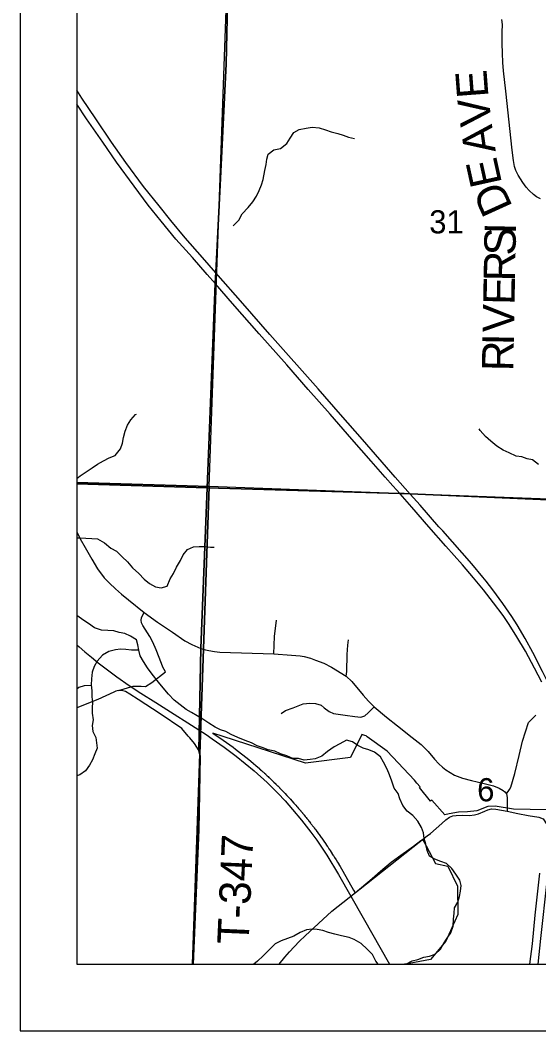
# Model space of a CAD drawing. Extents: x 0 to 34, y 0 to 22.
# Drawn here: x 2.735 to 3.672, y 14 to 15.827 of the extents above; entities that cross this region are included whole.
import ezdxf

# ---------------------------------------------------------------- set-up
doc = ezdxf.new("R2010")
doc.units = 0
for name, color, linetype in [('GM_X_Corporation', 7, 'Continuous'), ('GM_X_County_Road', 7, 'Continuous'), ('GM_X_Minor_River', 7, 'Continuous'), ('GM_X_Rail_Line', 7, 'Continuous'), ('GM_X_Section_Text', 7, 'Continuous'), ('GM_X_State_Route', 7, 'Continuous'), ('GM_X_Township_Road', 7, 'Continuous'), ('GM_X_Township_Road_Text', 7, 'Continuous'), ('SH_Data', 7, 'Continuous')]:
    doc.layers.add(name, color=color, linetype=linetype)

msp = doc.modelspace()

# ---------------------------------------------------------------- linework, layer by layer
at = {"layer": 'GM_X_Corporation'}
for points in [[(7.1023, 20.9204), (2.837, 20.9204), (2.837, 14.1204), (9.637, 14.1204), (9.637, 20.9204), (9.4036, 20.9204), (9.4022, 20.8667), (9.2273, 20.8723), (9.1354, 20.8749), (9.124, 20.8753), (8.9858, 20.878), (8.9676, 20.8785), (8.8663, 20.881), (8.6259, 20.8892), (8.5535, 20.8914), (8.5421, 20.8915), (8.4667, 20.8934), (8.0602, 20.9055), (7.9522, 20.9084), (7.1104, 20.9188)], [(3.3169, 20.9204), (2.837, 20.9204), (2.837, 14.9888), (3.0725, 14.9816), (3.0874, 15.351), (3.0879, 15.3623), (3.0883, 15.3712), (3.1072, 15.7483), (3.1177, 16.2414), (3.14, 16.6736), (3.1852, 17.7826), (3.1864, 17.8248), (3.233, 19.0394), (3.2586, 19.6098), (3.2623, 19.6596), (3.2721, 19.8755), (3.2728, 19.892), (3.2744, 19.9301), (3.2774, 20.0014), (3.2794, 20.0412), (3.3026, 20.5526), (3.3089, 20.7046), (3.3168, 20.9187)], [(2.837, 16.015), (2.837, 14.9913), (3.0765, 14.9841), (3.1126, 15.9984), (3.1125, 16.0117)], [(3.1126, 15.9984), (4.1402, 15.964), (4.1106, 14.9455), (3.0765, 14.9841)], [(2.837, 14.9913), (2.837, 14.1204), (3.0463, 14.1204), (3.0765, 14.9841)], [(2.837, 14.9888), (2.837, 14.1204), (3.0474, 14.1204), (3.0575, 14.3635), (3.0603, 14.4964), (3.0579, 14.5066), (3.0614, 14.6917), (3.0725, 14.9816)], [(3.0463, 14.1204), (4.0849, 14.1204), (4.1106, 14.9455), (3.0765, 14.9841)]]:
    msp.add_lwpolyline(points, close=True, dxfattribs=at)
for points in [[(3.1177, 16.2414), (3.1072, 15.7483), (3.0883, 15.3712), (3.0879, 15.3623), (3.0874, 15.351), (3.0725, 14.9816), (3.4212, 14.9717), (3.4288, 14.9714), (3.4395, 14.971), (3.7996, 14.9551), (3.9669, 14.9486), (3.9713, 14.9485), (4.1071, 14.9452), (4.1362, 14.9446), (4.18, 14.9435), (4.3471, 14.9395), (4.3478, 14.9395), (4.5297, 14.9322), (4.6565, 14.9275), (4.7295, 14.9251), (4.867, 14.9223), (4.9627, 14.9176), (5.1335, 14.9126), (5.2181, 14.9126)], [(3.7996, 14.9551), (3.4395, 14.971), (3.4288, 14.9714), (3.4212, 14.9717), (3.0725, 14.9816), (3.0614, 14.6917), (3.0579, 14.5066), (3.0603, 14.4964), (3.0575, 14.3635), (3.0474, 14.1204), (9.2101, 14.1204)], [(3.7781, 14.3976), (3.6263, 14.4007), (3.5933, 14.4061), (3.5799, 14.4055), (3.5598, 14.3975), (3.5434, 14.3962), (3.5268, 14.3952), (3.5099, 14.3924), (3.5025, 14.3905), (3.4788, 14.4172), (3.4766, 14.4155), (3.4565, 14.4402), (3.4578, 14.4411), (3.4519, 14.448), (3.4472, 14.4535), (3.3978, 14.5056), (3.3617, 14.5318), (3.3599, 14.5331), (3.3579, 14.5338), (3.352, 14.5359), (3.332, 14.4945), (3.2507, 14.4837), (3.1016, 14.5322), (3.0833, 14.5383), (3.1019, 14.5257), (3.12, 14.5126), (3.124, 14.5095), (3.1478, 14.4907), (3.1515, 14.4876), (3.1568, 14.4831), (3.1605, 14.48), (3.1671, 14.4742), (3.1674, 14.4739), (3.1692, 14.4723), (3.1693, 14.4722), (3.171, 14.4707), (3.1715, 14.4703), (3.1727, 14.4691), (3.1736, 14.4683), (3.1744, 14.4676), (3.1762, 14.466), (3.1779, 14.4644), (3.178, 14.4643), (3.1796, 14.4628), (3.1801, 14.4624), (3.1814, 14.4612), (3.1831, 14.4596), (3.1844, 14.4583), (3.1848, 14.4579), (3.1865, 14.4563), (3.1899, 14.4531), (3.1899, 14.453), (3.1901, 14.4529), (3.1933, 14.4498), (3.1933, 14.4497), (3.1935, 14.4496), (3.1966, 14.4465), (3.1967, 14.4464), (3.1969, 14.4462), (3.1999, 14.4432), (3.2001, 14.4431), (3.2003, 14.4429), (3.2032, 14.4399), (3.2034, 14.4397), (3.2037, 14.4395), (3.2065, 14.4365), (3.2067, 14.4363), (3.207, 14.436), (3.2098, 14.4331), (3.2103, 14.4326), (3.213, 14.4298), (3.2136, 14.4292), (3.2162, 14.4263), (3.2166, 14.426), (3.2168, 14.4257), (3.2194, 14.4229), (3.2198, 14.4225), (3.22, 14.4222), (3.2226, 14.4194), (3.223, 14.419), (3.2233, 14.4187), (3.2258, 14.416), (3.2262, 14.4155), (3.2264, 14.4152), (3.2289, 14.4125), (3.2293, 14.412), (3.2296, 14.4117), (3.232, 14.409), (3.2325, 14.4084), (3.2327, 14.4081), (3.2351, 14.4054), (3.2356, 14.4048), (3.2358, 14.4045), (3.2381, 14.4019), (3.2387, 14.4012), (3.2389, 14.4009), (3.2401, 14.3996), (3.2412, 14.3983), (3.2418, 14.3976), (3.242, 14.3973), (3.2431, 14.396), (3.2442, 14.3947), (3.2448, 14.394), (3.245, 14.3937), (3.2461, 14.3924), (3.2472, 14.3911), (3.2478, 14.3903), (3.2481, 14.39), (3.2486, 14.3894), (3.2487, 14.3893), (3.25, 14.3876), (3.2508, 14.3866), (3.251, 14.3863), (3.2514, 14.3859), (3.2516, 14.3856), (3.2528, 14.3842), (3.2538, 14.3829), (3.254, 14.3827), (3.2546, 14.382), (3.2556, 14.3807), (3.256, 14.3801), (3.2567, 14.3792), (3.257, 14.379), (3.2597, 14.3755), (3.2604, 14.3746), (3.261, 14.3738), (3.2618, 14.3727), (3.2623, 14.372), (3.2626, 14.3717), (3.2632, 14.3709), (3.2637, 14.3703), (3.2647, 14.369), (3.265, 14.3686), (3.2654, 14.368), (3.2661, 14.3671), (3.2663, 14.3668), (3.2675, 14.3652), (3.2676, 14.3651), (3.2683, 14.3642), (3.2689, 14.3634), (3.2711, 14.3604), (3.2717, 14.3596), (3.2739, 14.3565), (3.2745, 14.3558), (3.2767, 14.3527), (3.2772, 14.352), (3.2795, 14.3488), (3.2799, 14.3482), (3.2822, 14.3449), (3.2849, 14.341), (3.2853, 14.3405), (3.2876, 14.3371), (3.2879, 14.3366), (3.2902, 14.3332), (3.2906, 14.3327), (3.2929, 14.3292), (3.2955, 14.3253), (3.2957, 14.3249), (3.298, 14.3213), (3.2983, 14.3209), (3.3006, 14.3173), (3.3008, 14.317), (3.3031, 14.3133), (3.3056, 14.3092), (3.3058, 14.309), (3.3081, 14.3052), (3.3082, 14.305), (3.3105, 14.3011), (3.3106, 14.301), (3.313, 14.297), (3.313, 14.297), (3.3154, 14.2929), (3.3154, 14.2929), (3.3177, 14.2888), (3.3372, 14.2543), (3.34, 14.2493), (3.3709, 14.2756), (3.386, 14.2885), (3.4055, 14.3052), (3.4188, 14.3148), (3.4455, 14.3342), (3.459, 14.3439), (3.462, 14.3461), (3.4623, 14.3455), (3.4638, 14.3427), (3.4647, 14.341), (3.4683, 14.3344), (3.4683, 14.3344), (3.4854, 14.3027), (3.5074, 14.2976), (3.5254, 14.2616), (3.5257, 14.2102), (3.5043, 14.1621), (3.4763, 14.129), (3.4381, 14.122), (3.4295, 14.1204), (5.4145, 14.1204)]]:
    msp.add_lwpolyline(points, dxfattribs=at)
at = {"layer": 'GM_X_County_Road'}
for points in [[(2.837, 14.9023), (2.8435, 14.8895), (2.8522, 14.8741), (2.8643, 14.8525), (2.8748, 14.8351), (2.8867, 14.8193), (2.8962, 14.8092), (2.9071, 14.7992), (2.9182, 14.7892), (2.9304, 14.7792), (2.9588, 14.7565), (2.9832, 14.7388), (3.01, 14.7207), (3.0327, 14.7052), (3.045, 14.6982), (3.0616, 14.6911), (3.0699, 14.6889)], [(3.0699, 14.6889), (3.076, 14.6875), (3.0862, 14.6859), (3.0958, 14.6848), (3.1933, 14.6814), (3.2254, 14.6793), (3.2406, 14.6781), (3.2482, 14.6767), (3.2596, 14.6737), (3.2686, 14.6704), (3.2833, 14.6646), (3.2977, 14.6577), (3.3238, 14.6415), (3.334, 14.6317), (3.3549, 14.607), (3.3646, 14.5959), (3.3745, 14.5861), (3.3969, 14.5674), (3.4167, 14.5516), (3.4434, 14.5304), (3.4594, 14.5178), (3.4655, 14.5117), (3.4723, 14.5049), (3.4834, 14.4914), (3.4912, 14.4828), (3.4978, 14.4767), (3.504, 14.4721), (3.5195, 14.4625), (3.5342, 14.4571), (3.5502, 14.4524), (3.5711, 14.4475), (3.59, 14.4427), (3.6007, 14.439), (3.6077, 14.4348), (3.6105, 14.4321), (3.6134, 14.4283), (3.6149, 14.4216), (3.6151, 14.412), (3.6149, 14.3969)]]:
    msp.add_lwpolyline(points, dxfattribs=at)
at = {"layer": 'GM_X_Minor_River'}
for points in [[(3.1199, 15.4552), (3.1297, 15.4654), (3.1361, 15.4769), (3.147, 15.4887), (3.1553, 15.4986), (3.1621, 15.5088), (3.167, 15.5195), (3.1711, 15.5294), (3.1737, 15.5392), (3.1771, 15.5552), (3.1793, 15.5662), (3.1808, 15.5757), (3.183, 15.5852), (3.1932, 15.5928), (3.2053, 15.5952), (3.217, 15.6043), (3.2227, 15.6138), (3.2291, 15.6241), (3.2393, 15.6298), (3.2518, 15.6318), (3.2628, 15.6337), (3.2749, 15.6326), (3.2867, 15.6289), (3.2966, 15.6251), (3.3087, 15.6221), (3.3186, 15.6191), (3.3281, 15.6154), (3.3391, 15.6131)], [(2.837, 14.9984), (2.8433, 15.0032), (2.8648, 15.0177), (2.8747, 15.0245), (2.8853, 15.0303), (2.8955, 15.036), (2.9068, 15.0402), (2.9162, 15.052), (2.92, 15.0627), (2.9218, 15.0729), (2.9244, 15.0839), (2.9286, 15.095), (2.9346, 15.1045), (2.9433, 15.114), (2.9448, 15.1151)], [(3.6717, 15.0237), (3.6607, 15.0324), (3.6512, 15.0339), (3.6413, 15.0376), (3.6311, 15.0387), (3.6185, 15.0448), (3.6079, 15.05), (3.5965, 15.0572), (3.5854, 15.0659), (3.5755, 15.0746), (3.5664, 15.0852), (3.5645, 15.0882)], [(2.837, 14.8916), (2.8427, 14.8912), (2.8533, 14.8905), (2.8643, 14.8901), (2.8745, 14.8894), (2.8871, 14.8822), (2.8985, 14.8728), (2.9088, 14.8671), (2.919, 14.8569), (2.9289, 14.8482), (2.9377, 14.8369), (2.9491, 14.8267), (2.9587, 14.8168), (2.9686, 14.8085), (2.9796, 14.8025), (2.9894, 14.801), (3.0004, 14.8037), (3.0057, 14.817), (3.0121, 14.8269), (3.0173, 14.8383), (3.0245, 14.8501), (3.0297, 14.8607), (3.0373, 14.8703), (3.0483, 14.8752), (3.0585, 14.8757), (3.0684, 14.8757), (3.079, 14.8746), (3.0854, 14.8746)], [(3.1527, 14.5207), (3.1413, 14.5252), (3.1283, 14.5301), (3.1162, 14.5357), (3.1063, 14.541), (3.0968, 14.5444), (3.0873, 14.5489), (3.0755, 14.5565), (3.0652, 14.5633), (3.0546, 14.5697), (3.0443, 14.5753), (3.0348, 14.581), (3.0242, 14.5893), (3.0131, 14.598), (3.0032, 14.609), (2.9933, 14.6203), (2.9849, 14.6305), (2.9731, 14.6449), (2.9651, 14.6563), (2.9578, 14.668), (2.9517, 14.6779), (2.949, 14.6881), (2.9475, 14.6976), (2.9448, 14.7071), (2.9345, 14.7135), (2.9242, 14.7184), (2.9136, 14.7202), (2.9041, 14.7232), (2.8931, 14.724), (2.8817, 14.7243), (2.8692, 14.7288), (2.8582, 14.7364), (2.8483, 14.7428), (2.8388, 14.75), (2.837, 14.7511)], [(2.949, 14.6882), (2.9361, 14.6881), (2.9259, 14.6895), (2.9164, 14.6899), (2.9069, 14.6891), (2.8948, 14.686), (2.8835, 14.6791), (2.874, 14.6685), (2.8688, 14.6586), (2.865, 14.6487), (2.8636, 14.6365), (2.8632, 14.6255), (2.8644, 14.6145), (2.8641, 14.6039), (2.8657, 14.594), (2.8649, 14.5838), (2.865, 14.5743), (2.8669, 14.5622), (2.8647, 14.5523), (2.8659, 14.5413), (2.8713, 14.5303), (2.8728, 14.5208), (2.874, 14.5113), (2.8695, 14.501), (2.8654, 14.49), (2.8601, 14.4805), (2.853, 14.4699), (2.8428, 14.463), (2.837, 14.4612)], [(2.8633, 14.6246), (2.8507, 14.624), (2.8409, 14.6205), (2.837, 14.6177)], [(3.4326, 14.1204), (3.4332, 14.1213), (3.4434, 14.1266), (3.4536, 14.1293), (3.4646, 14.1335), (3.4748, 14.1351), (3.4847, 14.1385), (3.4945, 14.1477), (3.4998, 14.1572), (3.5065, 14.1678), (3.5133, 14.1774), (3.5174, 14.1895), (3.5181, 14.2017), (3.5192, 14.2127), (3.5199, 14.2226), (3.526, 14.2324), (3.5289, 14.2431), (3.5308, 14.2526), (3.5319, 14.2628), (3.5292, 14.2727), (3.5223, 14.2833), (3.5151, 14.2935), (3.5052, 14.3026), (3.4953, 14.3064), (3.4843, 14.3105), (3.4744, 14.3158), (3.4705, 14.326), (3.4678, 14.3374), (3.4651, 14.348), (3.4639, 14.3579), (3.4601, 14.3677), (3.4532, 14.3791), (3.4445, 14.3893), (3.4342, 14.3969), (3.4262, 14.4075), (3.4212, 14.4192), (3.4181, 14.4291), (3.4109, 14.4389), (3.4063, 14.4514), (3.402, 14.4628), (3.3978, 14.473), (3.3917, 14.4855), (3.386, 14.4954), (3.3749, 14.5041), (3.3651, 14.5078), (3.3544, 14.5112), (3.3449, 14.5161), (3.3354, 14.5225), (3.3248, 14.5255), (3.3127, 14.519), (3.3021, 14.5133), (3.2904, 14.5049), (3.2798, 14.4965), (3.2681, 14.4915), (3.2586, 14.4907), (3.248, 14.4892), (3.2377, 14.4925), (3.2275, 14.4925), (3.2168, 14.4974), (3.2054, 14.5008), (3.1948, 14.5057), (3.183, 14.5083), (3.1724, 14.512), (3.1629, 14.5154), (3.1527, 14.5207)], [(3.3816, 14.1204), (3.3774, 14.126), (3.3713, 14.1381), (3.3618, 14.1479), (3.3511, 14.1582), (3.3386, 14.1649), (3.3291, 14.1687), (3.3154, 14.1721), (3.3033, 14.1747), (3.2923, 14.1781), (3.282, 14.1814), (3.2718, 14.1833), (3.2623, 14.184), (3.252, 14.1825), (3.2407, 14.1779), (3.2293, 14.1714), (3.218, 14.1668), (3.2066, 14.1629), (3.1957, 14.1572), (3.1836, 14.145), (3.1738, 14.1355), (3.1636, 14.1259), (3.1572, 14.1204)]]:
    msp.add_lwpolyline(points, dxfattribs=at)
at = {"layer": 'GM_X_Rail_Line'}
for points in [[(2.837, 14.6979), (2.8412, 14.6942), (2.852, 14.6852), (2.8638, 14.6754), (2.876, 14.6652), (2.9098, 14.6398), (2.932, 14.6243), (2.9528, 14.6105), (2.98, 14.5934), (3.0712, 14.5355), (3.082, 14.528), (3.1036, 14.5129), (3.1251, 14.4968), (3.1576, 14.4701), (3.1809, 14.4493), (3.2006, 14.4299), (3.2137, 14.4158), (3.2272, 14.4003), (3.2431, 14.3811), (3.26, 14.3595), (3.2708, 14.3448), (3.2892, 14.3175), (3.3101, 14.2827), (3.3546, 14.2046), (3.4022, 14.1204)], [(3.6944, 14.3472), (3.6867, 14.2704), (3.6753, 14.1667), (3.6706, 14.1204)], [(3.6561, 14.1204), (3.6604, 14.1571), (3.6657, 14.2089), (3.6741, 14.2851)]]:
    msp.add_lwpolyline(points, dxfattribs=at)
at = {"layer": 'GM_X_State_Route'}
for points in [[(3.4984, 14.9039), (3.4917, 14.9114), (3.4575, 14.9501), (3.4397, 14.9704), (3.4127, 15.0013), (3.3533, 15.0689), (3.3135, 15.1142), (3.2732, 15.1605), (3.1863, 15.259), (3.1374, 15.3152), (3.0885, 15.3707), (3.0644, 15.3981), (3.0333, 15.4339), (3.007, 15.4649), (2.9858, 15.4913), (2.9576, 15.5265), (2.9257, 15.57), (2.8996, 15.6069), (2.8713, 15.6486), (2.8464, 15.6859), (2.837, 15.7004)], [(3.6776, 14.6305), (3.6645, 14.6559), (3.648, 14.6866), (3.6324, 14.7121), (3.6183, 14.7348), (3.6076, 14.7509), (3.5899, 14.7738), (3.5722, 14.7975), (3.5541, 14.8192), (3.5344, 14.8426), (3.5043, 14.8765), (3.4735, 14.9112), (3.4424, 14.9465), (3.4214, 14.9711), (3.4085, 14.9854), (3.3942, 15.0013), (3.3694, 15.0299), (3.3342, 15.0699), (3.2949, 15.1148), (3.2551, 15.1597), (3.2166, 15.204), (3.1669, 15.2604), (3.1187, 15.3147), (3.0876, 15.3504), (3.073, 15.3673), (3.0461, 15.3982), (3.0164, 15.4315), (2.9899, 15.4637), (2.966, 15.493), (2.941, 15.5268), (2.9091, 15.5703), (2.8843, 15.6065), (2.8547, 15.6489), (2.837, 15.6754)], [(3.5767, 14.8127), (3.5707, 14.8205), (3.5508, 14.8442), (3.4984, 14.9039)], [(3.7036, 14.599), (3.6918, 14.6231), (3.6786, 14.6499), (3.6612, 14.6838), (3.6477, 14.7095), (3.6329, 14.7338), (3.6232, 14.7493), (3.6071, 14.7728), (3.5888, 14.7972), (3.5767, 14.8127)]]:
    msp.add_lwpolyline(points, dxfattribs=at)
at = {"layer": 'GM_X_Township_Road'}
msp.add_line((3.3607, 14.2658), (3.4706, 14.3526), dxfattribs=at)
for points in [[(3.6749, 15.5043), (3.668, 15.508), (3.6622, 15.5122), (3.6546, 15.519), (3.6495, 15.5255), (3.6433, 15.5339), (3.6347, 15.5471), (3.6303, 15.5553), (3.6279, 15.5627), (3.6262, 15.5733), (3.6238, 15.5924), (3.6122, 15.699), (3.6084, 15.7355), (3.6071, 15.7507), (3.6063, 15.7678), (3.606, 15.7848), (3.606, 15.8057), (3.6064, 15.8194), (3.6055, 15.8285)], [(2.9128, 14.6156), (2.939, 14.6233), (2.9538, 14.623), (2.9613, 14.6228), (2.973, 14.6296), (2.9977, 14.6488), (2.9928, 14.6575), (2.9901, 14.6641), (2.9808, 14.6887), (2.9747, 14.703), (2.969, 14.713), (2.9563, 14.7331), (2.954, 14.7378), (2.9534, 14.7423), (2.954, 14.7464), (2.9562, 14.751), (2.9588, 14.7565)], [(3.1933, 14.6814), (3.1944, 14.7132), (3.1981, 14.7424)], [(3.3238, 14.6415), (3.3252, 14.6496), (3.3259, 14.6803), (3.327, 14.6973), (3.3282, 14.707)], [(2.904, 14.6124), (2.875, 14.5992), (2.837, 14.5838)], [(2.9329, 14.6087), (2.9252, 14.6136), (2.9201, 14.6149), (2.9128, 14.6156), (2.9077, 14.6141), (2.904, 14.6124)], [(3.0413, 14.5297), (3.0387, 14.5328), (3.027, 14.5469), (2.9876, 14.5729), (2.9482, 14.5989), (2.9329, 14.6087)], [(3.2067, 14.574), (3.2142, 14.5794), (3.2283, 14.5842), (3.2463, 14.5911), (3.258, 14.5927), (3.2685, 14.5921), (3.279, 14.5888), (3.2845, 14.584), (3.2934, 14.5774), (3.301, 14.574), (3.3223, 14.5705), (3.3396, 14.5684), (3.3502, 14.5672), (3.3579, 14.5693), (3.364, 14.5749), (3.3745, 14.5861)], [(3.6134, 14.4283), (3.6193, 14.4361), (3.6218, 14.4406), (3.6285, 14.465), (3.6365, 14.4977), (3.6428, 14.5236), (3.6532, 14.5576), (3.6669, 14.5708)], [(3.0483, 14.1204), (3.0577, 14.363), (3.0605, 14.4958), (3.0581, 14.506), (3.0499, 14.5196), (3.0413, 14.5297)], [(3.4706, 14.3526), (3.4761, 14.357), (3.4863, 14.3659), (3.4967, 14.375), (3.5039, 14.3817), (3.5105, 14.3861), (3.517, 14.3885), (3.5229, 14.3894), (3.5346, 14.3897), (3.5468, 14.3894), (3.5558, 14.3903), (3.5633, 14.3926), (3.5745, 14.3969), (3.5802, 14.3993), (3.5867, 14.4013), (3.5944, 14.4008), (3.6149, 14.3969)], [(3.6149, 14.3969), (3.6339, 14.3931), (3.6528, 14.3893), (3.6723, 14.3861), (3.6798, 14.3831), (3.6922, 14.3648), (3.6955, 14.3589)], [(3.2027, 14.1204), (3.213, 14.1332), (3.2213, 14.143), (3.2299, 14.1522), (3.2397, 14.1622), (3.25, 14.1719), (3.2979, 14.2162), (3.3607, 14.2658)]]:
    msp.add_lwpolyline(points, dxfattribs=at)
at = {"layer": 'SH_Data'}
for p, q in [((2.7349, 21.0001), (2.7349, 14.0001)), ((2.7349, 14.0001), (9.7349, 14.0001))]:
    msp.add_line(p, q, dxfattribs=at)

# ---------------------------------------------------------------- texts
at = {"layer": 'GM_X_Section_Text'}
for s, height, p in [('31', 0.04186, (3.4741, 15.4417)), ('6', 0.0419, (3.5607, 14.415))]:
    msp.add_text(s, height=height, rotation=0, dxfattribs=at).set_placement(p)
at = {"layer": 'GM_X_Township_Road_Text'}
for s, height, rotation, p in [('E', 0.0568, 94.3326, (3.5813, 15.6883)), ('V', 0.0568, 97.074, (3.5873, 15.6394)), ('A', 0.0568, 98.0662, (3.5943, 15.5901)), ('E', 0.0568, 102.4405, (3.6058, 15.5324)), ('D', 0.0568, 114.4381, (3.6255, 15.4899)), ('S', 0.0568, 88.9071, (3.6299, 15.4014)), ('I', 0.0568, 88.91, (3.6306, 15.4397)), ('R', 0.0568, 88.9085, (3.629, 15.3547)), ('E', 0.0568, 88.9075, (3.6282, 15.3122)), ('V', 0.0568, 88.9071, (3.6272, 15.2623)), ('R', 0.0568, 88.9071, (3.6259, 15.1923)), ('I', 0.0568, 88.9085, (3.6268, 15.2389)), ('T-347', 0.05682, 87.4742, (3.1476, 14.1556))]:
    msp.add_text(s, height=height, rotation=rotation, dxfattribs=at).set_placement(p)

doc.saveas('drawing.dxf')
